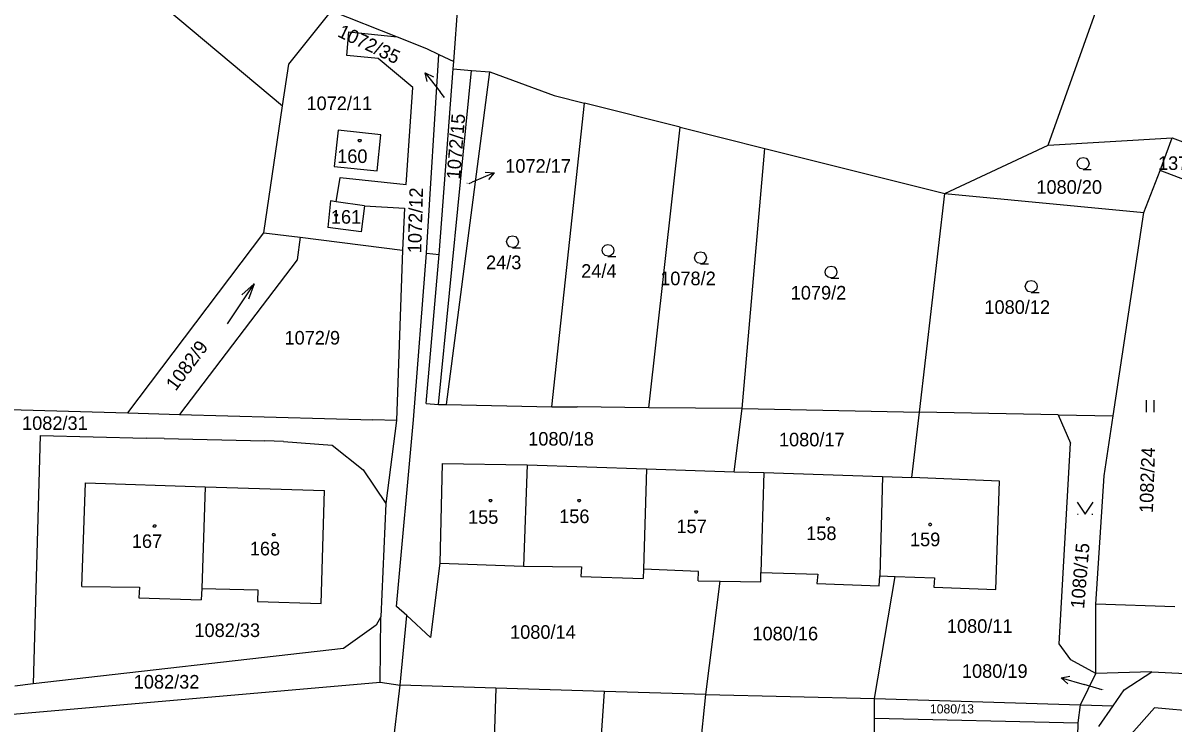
# Model space of a CAD drawing. Extents: x -852001 to -842497, y -1063614 to -1052182.
# Drawn here: x -849566 to -849422.1, y -1056257.6 to -1056170 of the extents above; entities that cross this region are included whole.
import ezdxf

# ---------------------------------------------------------------- set-up
doc = ezdxf.new("R2010")
doc.units = 0
for name, color, linetype in [('Default', 7, 'Continuous'), ('KN_HRANICE', 7, 'Continuous'), ('KN_KULTURY', 7, 'Continuous'), ('KN_PARCELY', 7, 'Continuous')]:
    doc.layers.add(name, color=color, linetype=linetype)

# ---------------------------------------------------------------- blocks, each defined once
blk = doc.blocks.new('304')
at = {"layer": 'Default'}
blk.add_lwpolyline([(0, 0), (-0.38, 0.1), (-0.65, 0.37), (-0.75, 0.74), (-0.65, 1.11), (-0.38, 1.38), (-0.01, 1.48), (0.36, 1.38), (0.63, 1.11), (0.73, 0.73), (0.63, 0.35), (0.36, 0.08), (-0.02, -0.02), (0.98, -0.02)], dxfattribs=at)
blk = doc.blocks.new('306')
at = {"layer": 'Default'}
for p, q in [((-0.5, 1.5), (-0.5, 0)), ((0.5, 0), (0.5, 1.5))]:
    blk.add_line(p, q, dxfattribs=at)
blk = doc.blocks.new('314')
at = {"layer": 'Default'}
for p, q in [((-0.95, 0), (-0.85, 0)), ((0.85, 0), (0.95, 0))]:
    blk.add_line(p, q, dxfattribs=at)
blk.add_lwpolyline([(-1, 1.5), (0, 0), (1, 1.5)], dxfattribs=at)
blk = doc.blocks.new('802')
at = {"layer": 'Default'}
blk.add_line((-3, 0), (3, 0), dxfattribs=at)
blk.add_lwpolyline([(1, 0.5), (3, 0), (1, -0.5)], dxfattribs=at)
blk = doc.blocks.new('10292')
at = {"layer": 'Default'}
blk.add_line((0, 3), (0, 0), dxfattribs=at)
blk.add_lwpolyline([(-0.5, 2), (0, 3), (0.5, 2)], dxfattribs=at)
blk = doc.blocks.new('402')
at = {"layer": 'Default'}
blk.add_lwpolyline([(0.09, 0.15), (0.18, 0), (0.09, -0.15), (-0.09, -0.15), (-0.18, 0), (-0.09, 0.15), (0.09, 0.15)], dxfattribs=at)

msp = doc.modelspace()

# ---------------------------------------------------------------- linework, layer by layer
at = {"layer": 'KN_HRANICE'}
for p, q in [((-849437.73, -1056185.24), (-849425.04, -1056149.71)), ((-849565.73, -1056153.32), (-849533.49, -1056180.31)), ((-849532.73, -1056175.12), (-849527.38, -1056168.45)), ((-849527.38, -1056168.45), (-849519.17, -1056171.69)), ((-849512.08, -1056174.78), (-849511.52, -1056167.35)), ((-849525.47, -1056174.02), (-849525.23, -1056171.06)), ((-849525.23, -1056171.06), (-849519.17, -1056171.69)), ((-849519.17, -1056171.69), (-849515.51, -1056173.13)), ((-849521.53, -1056174.4), (-849525.47, -1056174.02)), ((-849517.22, -1056178.04), (-849521.53, -1056174.4)), ((-849515.51, -1056173.13), (-849513.93, -1056173.89)), ((-849515.49, -1056198.73), (-849513.93, -1056173.89)), ((-849513.93, -1056173.89), (-849512.08, -1056174.78)), ((-849533.49, -1056180.31), (-849532.73, -1056175.12)), ((-849513.9, -1056198.93), (-849512.15, -1056175.71)), ((-849512.15, -1056175.71), (-849512.08, -1056174.78)), ((-849512.15, -1056175.71), (-849509.86, -1056175.89)), ((-849513.99, -1056217.66), (-849509.86, -1056175.89)), ((-849512.99, -1056217.67), (-849507.57, -1056176.06)), ((-849509.86, -1056175.89), (-849507.57, -1056176.06)), ((-849507.57, -1056176.06), (-849499.52, -1056179.04)), ((-849518.02, -1056190.16), (-849517.22, -1056178.04)), ((-849499.82, -1056217.95), (-849495.72, -1056180)), ((-849499.52, -1056179.04), (-849495.72, -1056180)), ((-849483.74, -1056183), (-849495.72, -1056180)), ((-849535.83, -1056196.19), (-849533.49, -1056180.31)), ((-849487.67, -1056218.08), (-849483.74, -1056183)), ((-849483.74, -1056183), (-849473.17, -1056185.65)), ((-849526.56, -1056183.37), (-849527.04, -1056187.89)), ((-849521.2, -1056183.94), (-849526.56, -1056183.37)), ((-849521.67, -1056188.46), (-849521.2, -1056183.94)), ((-849437.73, -1056185.24), (-849422.22, -1056184.31)), ((-849423.72, -1056188.39), (-849422.22, -1056184.31)), ((-849422.22, -1056184.31), (-849418.99, -1056185.55)), ((-849476.02, -1056218.16), (-849473.17, -1056185.65)), ((-849473.17, -1056185.65), (-849450.63, -1056191.3)), ((-849450.63, -1056191.3), (-849437.73, -1056185.24)), ((-849527.04, -1056187.89), (-849521.67, -1056188.46)), ((-849425.74, -1056193.65), (-849423.72, -1056188.39)), ((-849420.56, -1056189.61), (-849423.72, -1056188.39)), ((-849526.8, -1056192.31), (-849526.31, -1056189.3)), ((-849526.31, -1056189.3), (-849518.02, -1056190.16)), ((-849453.82, -1056218.63), (-849450.63, -1056191.3)), ((-849450.63, -1056191.3), (-849425.74, -1056193.65)), ((-849527.49, -1056192.21), (-849527.83, -1056195.55)), ((-849526.8, -1056192.31), (-849527.49, -1056192.21)), ((-849523.27, -1056192.83), (-849526.8, -1056192.31)), ((-849523.27, -1056192.83), (-849523.66, -1056196.06)), ((-849523.27, -1056192.83), (-849518.25, -1056193.14)), ((-849518.25, -1056193.14), (-849518.5, -1056198.37)), ((-849429.59, -1056219.1), (-849425.74, -1056193.65)), ((-849523.66, -1056196.06), (-849527.83, -1056195.55)), ((-849552.87, -1056218.73), (-849535.83, -1056196.19)), ((-849535.83, -1056196.19), (-849531.3, -1056196.76)), ((-849531.3, -1056196.76), (-849531.68, -1056199.6)), ((-849531.3, -1056196.76), (-849518.5, -1056198.37)), ((-849518.5, -1056198.37), (-849519.23, -1056219.66)), ((-849517.12, -1056219.58), (-849515.49, -1056198.73)), ((-849515.49, -1056198.73), (-849513.9, -1056198.93)), ((-849531.68, -1056199.6), (-849546.39, -1056218.91)), ((-849515.53, -1056217.54), (-849513.9, -1056198.93)), ((-849515.53, -1056217.54), (-849513.99, -1056217.66)), ((-849592.97, -1056217.6), (-849552.87, -1056218.73)), ((-849552.87, -1056218.73), (-849546.39, -1056218.91)), ((-849546.39, -1056218.91), (-849522.19, -1056219.6)), ((-849513.99, -1056217.66), (-849512.99, -1056217.67)), ((-849512.99, -1056217.67), (-849499.82, -1056217.95)), ((-849499.82, -1056217.95), (-849496.64, -1056217.95)), ((-849487.67, -1056218.08), (-849496.64, -1056217.95)), ((-849476.02, -1056218.16), (-849487.67, -1056218.08)), ((-849477.02, -1056226.08), (-849476.02, -1056218.16)), ((-849476.02, -1056218.16), (-849453.82, -1056218.63)), ((-849454.77, -1056226.8), (-849453.82, -1056218.63)), ((-849436.49, -1056218.97), (-849453.82, -1056218.63)), ((-849436.49, -1056218.97), (-849429.59, -1056219.1)), ((-849436.49, -1056218.97), (-849434.92, -1056222.51)), ((-849519.23, -1056219.66), (-849522.19, -1056219.6)), ((-849519.23, -1056219.66), (-849520.58, -1056230.06)), ((-849519.24, -1056242.93), (-849517.12, -1056219.58)), ((-849430.73, -1056226.62), (-849429.59, -1056219.1)), ((-849563.83, -1056221.55), (-849564.68, -1056252.6)), ((-849563.83, -1056221.55), (-849550.57, -1056221.9)), ((-849548.32, -1056221.93), (-849550.57, -1056221.9)), ((-849548.32, -1056221.93), (-849535.73, -1056222.24)), ((-849533.4, -1056222.32), (-849535.73, -1056222.24)), ((-849533.4, -1056222.32), (-849527.28, -1056222.76)), ((-849527.28, -1056222.76), (-849523.4, -1056225.85)), ((-849436.33, -1056247.63), (-849434.92, -1056222.51)), ((-849523.4, -1056225.85), (-849520.58, -1056230.06)), ((-849513.55, -1056225.07), (-849513.82, -1056237.54)), ((-849513.55, -1056225.07), (-849502.89, -1056225.24)), ((-849502.89, -1056225.24), (-849503.37, -1056237.88)), ((-849502.89, -1056225.24), (-849487.95, -1056225.73)), ((-849487.95, -1056225.73), (-849488.36, -1056238.28)), ((-849487.95, -1056225.73), (-849477.02, -1056226.08)), ((-849477.02, -1056226.08), (-849473.29, -1056226.2)), ((-849473.29, -1056226.2), (-849473.65, -1056238.68)), ((-849473.29, -1056226.2), (-849458.46, -1056226.68)), ((-849558.62, -1056240.45), (-849558.17, -1056227.46)), ((-849558.17, -1056227.46), (-849543.2, -1056227.96)), ((-849458.46, -1056226.68), (-849458.8, -1056239.11)), ((-849458.46, -1056226.68), (-849454.77, -1056226.8)), ((-849443.79, -1056227.26), (-849454.77, -1056226.8)), ((-849444.27, -1056240.81), (-849443.79, -1056227.26)), ((-849431.74, -1056242.65), (-849430.73, -1056226.62)), ((-849543.2, -1056227.96), (-849543.62, -1056240.68)), ((-849543.2, -1056227.96), (-849528.27, -1056228.45)), ((-849528.65, -1056242.55), (-849528.27, -1056228.45)), ((-849520.58, -1056230.06), (-849521.22, -1056244.23)), ((-849513.82, -1056237.54), (-849514.98, -1056246.81)), ((-849513.82, -1056237.54), (-849503.37, -1056237.88)), ((-849503.37, -1056237.88), (-849496.11, -1056238)), ((-849496.11, -1056238), (-849496.18, -1056239.18)), ((-849488.36, -1056238.28), (-849488.39, -1056239.42)), ((-849481.46, -1056238.55), (-849488.36, -1056238.28)), ((-849481.51, -1056239.72), (-849481.46, -1056238.55)), ((-849473.68, -1056239.87), (-849473.65, -1056238.68)), ((-849473.65, -1056238.68), (-849466.55, -1056238.91)), ((-849466.55, -1056238.91), (-849466.66, -1056240.06)), ((-849459.44, -1056254.46), (-849456.85, -1056239.17)), ((-849458.87, -1056240.34), (-849458.8, -1056239.11)), ((-849458.8, -1056239.11), (-849456.85, -1056239.17)), ((-849456.85, -1056239.17), (-849451.95, -1056239.35)), ((-849558.62, -1056240.45), (-849551.38, -1056240.51)), ((-849551.38, -1056240.51), (-849551.46, -1056241.87)), ((-849496.18, -1056239.18), (-849488.39, -1056239.42)), ((-849481.51, -1056239.72), (-849478.74, -1056239.77)), ((-849480.53, -1056253.97), (-849478.74, -1056239.77)), ((-849478.74, -1056239.77), (-849473.68, -1056239.87)), ((-849466.66, -1056240.06), (-849458.87, -1056240.34)), ((-849451.95, -1056239.35), (-849452.03, -1056240.54)), ((-849452.03, -1056240.54), (-849444.27, -1056240.81)), ((-849551.46, -1056241.87), (-849543.67, -1056242.12)), ((-849543.62, -1056240.68), (-849543.67, -1056242.12)), ((-849543.62, -1056240.68), (-849536.61, -1056240.84)), ((-849536.61, -1056240.84), (-849536.64, -1056242.31)), ((-849536.64, -1056242.31), (-849528.65, -1056242.55)), ((-849517.97, -1056244.08), (-849519.24, -1056242.93)), ((-849431.76, -1056251.31), (-849431.74, -1056242.65)), ((-849421.86, -1056243), (-849431.74, -1056242.65)), ((-849521.22, -1056244.23), (-849521.78, -1056245.26)), ((-849521.28, -1056252.42), (-849521.22, -1056244.23)), ((-849518.79, -1056252.77), (-849517.97, -1056244.08)), ((-849514.98, -1056246.81), (-849517.97, -1056244.08)), ((-849521.78, -1056245.26), (-849525.87, -1056248.18)), ((-849434.87, -1056249.61), (-849436.33, -1056247.63)), ((-849525.87, -1056248.18), (-849564.68, -1056252.6)), ((-849431.76, -1056251.31), (-849434.87, -1056249.61)), ((-849433.67, -1056255.23), (-849431.76, -1056251.31)), ((-849424.74, -1056251.13), (-849431.76, -1056251.31)), ((-849428.22, -1056253.36), (-849424.74, -1056251.13)), ((-849424.74, -1056251.13), (-849362.03, -1056254.15)), ((-849572.97, -1056256.89), (-849521.28, -1056252.42)), ((-849564.68, -1056252.6), (-849567, -1056252.9)), ((-849521.28, -1056252.42), (-849518.79, -1056252.77)), ((-849520.73, -1056268.91), (-849518.79, -1056252.77)), ((-849506.8, -1056253.15), (-849518.79, -1056252.77)), ((-849506.8, -1056253.15), (-849508.04, -1056289.59)), ((-849493.22, -1056253.57), (-849506.8, -1056253.15)), ((-849429.59, -1056255.35), (-849428.22, -1056253.36)), ((-849494.45, -1056270.95), (-849493.22, -1056253.57)), ((-849480.53, -1056253.97), (-849493.22, -1056253.57)), ((-849482.35, -1056270.93), (-849480.53, -1056253.97)), ((-849480.53, -1056253.97), (-849459.44, -1056254.46)), ((-849459.46, -1056256.93), (-849459.44, -1056254.46)), ((-849459.44, -1056254.46), (-849433.67, -1056255.23)), ((-849433.96, -1056257.48), (-849433.67, -1056255.23)), ((-849433.67, -1056255.23), (-849429.59, -1056255.35)), ((-849431.37, -1056257.95), (-849429.59, -1056255.35)), ((-849424.4, -1056255.6), (-849428.61, -1056260.33)), ((-849404.18, -1056257.55), (-849424.4, -1056255.6)), ((-849459.61, -1056271.66), (-849459.46, -1056256.93)), ((-849459.46, -1056256.93), (-849433.96, -1056257.48)), ((-849434.27, -1056268.55), (-849433.96, -1056257.48))]:
    msp.add_line(p, q, dxfattribs=at)
at = {"layer": 'KN_PARCELY'}
for p, q in [((-849513.26, -1056179.26), (-849513.8, -1056178.56)), ((-849510.16, -1056190.04), (-849509.78, -1056189.88)), ((-849430.97, -1056253.37), (-849433.22, -1056252.71))]:
    msp.add_line(p, q, dxfattribs=at)

# ---------------------------------------------------------------- block references
at = {"layer": 'KN_KULTURY'}
for name, p in [('402', (-849523.86, -1056184.67)), ('304', (-849433.34, -1056188.25)), ('402', (-849526.8, -1056194)), ('304', (-849504.73, -1056198.05)), ('304', (-849492.78, -1056199.13)), ('304', (-849481.2, -1056200.06)), ('304', (-849464.87, -1056201.85)), ('304', (-849439.83, -1056203.64)), ('306', (-849424.97, -1056218.64)), ('402', (-849507.48, -1056229.7)), ('402', (-849496.39, -1056229.7)), ('314', (-849433.1, -1056231.38)), ('402', (-849481.76, -1056231.12)), ('402', (-849465.27, -1056231.98)), ('402', (-849549.51, -1056232.88)), ('402', (-849452.49, -1056232.69)), ('402', (-849534.6, -1056233.97))]:
    msp.add_blockref(name, p, dxfattribs=at)
at = {"layer": 'KN_KULTURY', "rotation": 56.60823000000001}
msp.add_blockref('802', (-849538.72, -1056205.07), dxfattribs=at)
at = {"layer": 'KN_PARCELY'}
for p, rotation in [((-849513.8, -1056178.56), 37.987102), ((-849509.78, -1056189.88), -66.64560900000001), ((-849433.22, -1056252.71), 73.682372)]:
    msp.add_blockref('10292', p, dxfattribs=dict(at, rotation=rotation))

# ---------------------------------------------------------------- texts
for s, rotation, p in [('1072/35', 334.378, (-849526.74, -1056171.59)), ('1072/15', 85.313, (-849511.31, -1056189.57)), ('1072/12', 88.407, (-849516.15, -1056198.78)), ('1082/9', 53.342, (-849546.87, -1056216.08)), ('1082/24', 88.006, (-849424.62, -1056231.27)), ('1080/15', 85.142, (-849433.23, -1056243.26))]:
    msp.add_text(s, height=1.7, rotation=rotation, dxfattribs=at).set_placement(p)
for s, height, p in [('1072/11', 1.7, (-849530.51, -1056180.85)), ('1072/35', 0.1, (-849513.61, -1056179.26)), ('160', 1.7, (-849526.67, -1056187.47)), ('1072/17', 1.7, (-849505.64, -1056188.69)), ('137', 1.7, (-849423.98, -1056188.34)), ('1072/17', 0.1, (-849510.51, -1056190.04)), ('1080/20', 1.7, (-849439.2, -1056191.32)), ('161', 1.7, (-849527.46, -1056195.06)), ('24/3', 1.7, (-849508.05, -1056200.75)), ('24/4', 1.7, (-849496.14, -1056201.83)), ('1078/2', 1.7, (-849486.26, -1056202.76)), ('1079/2', 1.7, (-849469.93, -1056204.55)), ('1080/12', 1.7, (-849445.7, -1056206.34)), ('1072/9', 1.7, (-849533.26, -1056210.18)), ('1082/31', 1.7, (-849566.09, -1056220.86)), ('1080/18', 1.7, (-849502.77, -1056222.82)), ('1080/17', 1.7, (-849471.4, -1056222.91)), ('155', 1.7, (-849510.3, -1056232.6)), ('156', 1.7, (-849498.9, -1056232.51)), ('157', 1.7, (-849484.22, -1056233.77)), ('158', 1.7, (-849467.99, -1056234.63)), ('167', 1.7, (-849552.36, -1056235.62)), ('168', 1.7, (-849537.6, -1056236.55)), ('159', 1.7, (-849455.01, -1056235.4)), ('1080/11', 1.7, (-849450.39, -1056246.24)), ('1082/33', 1.7, (-849544.53, -1056246.76)), ('1080/14', 1.7, (-849505.04, -1056246.98)), ('1080/16', 1.7, (-849474.72, -1056247.18)), ('1080/19', 1.7, (-849448.51, -1056251.87)), ('1082/32', 1.7, (-849552.12, -1056253.21)), ('1080/19', 0.1, (-849431.31, -1056253.37)), ('1080/13', 1.14, (-849452.51, -1056256.32))]:
    msp.add_text(s, height=height, dxfattribs=at).set_placement(p)

doc.saveas('drawing.dxf')
